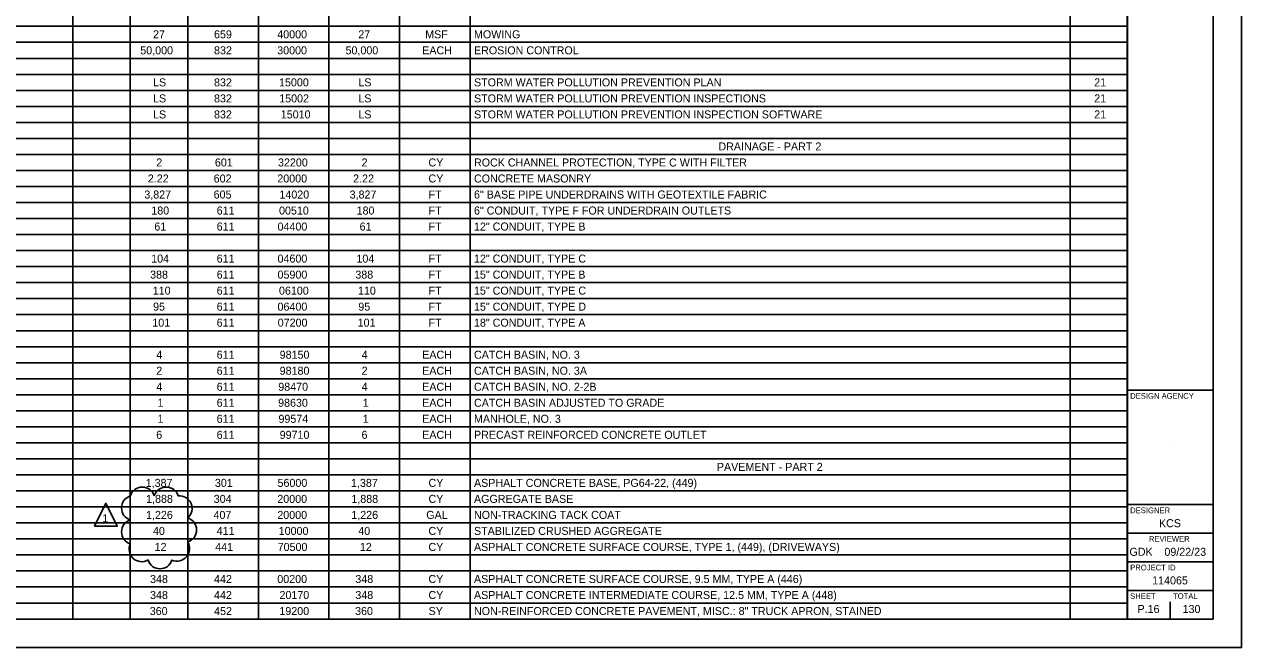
# Model space of a CAD drawing. Extents: x -156 to 77, y 0 to 24.
# Drawn here: x 12.71 to 34, y 0 to 10.89 of the extents above; entities that cross this region are included whole.
import ezdxf

# ---------------------------------------------------------------- set-up
doc = ezdxf.new("R2010")
doc.units = 0
for name, color, linetype in [('Default', 7, 'Continuous'), ('MU_Markup_Cloud', 7, 'Continuous'), ('SH_Border', 7, 'Continuous'), ('SH_Cut_Line', 7, 'Continuous'), ('SH_Data', 7, 'Continuous')]:
    doc.layers.add(name, color=color, linetype=linetype)

msp = doc.modelspace()

# ---------------------------------------------------------------- linework, layer by layer
at = {"layer": 'Default'}
for p, q in [((13.556, 21.5), (13.556, 0.5)), ((15.566, 21.5), (15.566, 0.5)), ((16.801, 21.5), (16.801, 0.5)), ((18.036, 21.5), (18.036, 0.5)), ((19.272, 21.5), (19.272, 0.5)), ((20.507, 21.5), (20.507, 0.5)), ((30.999, 21.5), (30.999, 0.5)), ((32.004, 21.5), (32.004, 0.5)), ((14.561, 20.94), (14.561, 0.5)), ((1.5, 10.86), (32.004, 10.86)), ((1.5, 10.58), (32.004, 10.58)), ((1.5, 10.3), (32.004, 10.3)), ((1.5, 10.02), (32.004, 10.02)), ((1.5, 9.74), (32.004, 9.74)), ((1.5, 9.46), (32.004, 9.46)), ((1.5, 9.18), (32.004, 9.18)), ((1.5, 8.9), (32.004, 8.9)), ((1.5, 8.62), (32.004, 8.62)), ((1.5, 8.34), (32.004, 8.34)), ((1.5, 8.06), (32.004, 8.06)), ((1.5, 7.78), (32.004, 7.78)), ((1.5, 7.5), (32.004, 7.5)), ((1.5, 7.22), (32.004, 7.22)), ((1.5, 6.94), (32.004, 6.94)), ((1.5, 6.66), (32.004, 6.66)), ((1.5, 6.38), (32.004, 6.38)), ((1.5, 6.1), (32.004, 6.1)), ((1.5, 5.82), (32.004, 5.82)), ((1.5, 5.54), (32.004, 5.54)), ((1.5, 5.26), (32.004, 5.26)), ((1.5, 4.98), (32.004, 4.98)), ((1.5, 4.7), (32.004, 4.7)), ((1.5, 4.42), (32.004, 4.42)), ((1.5, 4.14), (32.004, 4.14)), ((1.5, 3.86), (32.004, 3.86)), ((1.5, 3.58), (32.004, 3.58)), ((1.5, 3.3), (32.004, 3.3)), ((1.5, 3.02), (32.004, 3.02)), ((1.5, 2.74), (32.004, 2.74)), ((1.5, 2.46), (32.004, 2.46)), ((1.5, 2.18), (32.004, 2.18)), ((1.5, 1.9), (32.004, 1.9)), ((1.5, 1.62), (32.004, 1.62)), ((1.5, 1.34), (32.004, 1.34)), ((1.5, 1.06), (32.004, 1.06)), ((1.5, 0.78), (32.004, 0.78)), ((1.5, 0.5), (32.004, 0.5))]:
    msp.add_line(p, q, dxfattribs=at)
at = {"layer": 'MU_Markup_Cloud'}
msp.add_lwpolyline([(13.934, 2.123), (14.134, 2.523), (14.334, 2.123)], close=True, dxfattribs=at)
for centre, start, end in [((14.771, 2.586), 17.5, 162.5), ((15.19, 2.586), 17.5, 162.5), ((14.628, 2.442), 107.5, 252.5), ((15.422, 2.433), 310.8844, 95.8844), ((14.628, 2.023), 107.5, 252.5), ((15.5, 2.058), 287.5, 72.5), ((14.761, 1.722), 155.2877, 300.2877), ((15.379, 1.733), 246.4801, 31.4801), ((15.081, 1.598), 197.5, 342.5)]:
    msp.add_arc(centre, 0.22, start, end, dxfattribs=at)
at = {"layer": 'SH_Border'}
for p, q in [((32, 0.5), (32, 21.5)), ((32, 4.5), (33.5, 4.5)), ((32, 2.5), (33.5, 2.5)), ((32, 2), (33.5, 2)), ((32, 1.5), (33.5, 1.5)), ((32, 1), (33.5, 1))]:
    msp.add_line(p, q, dxfattribs=at)
msp.add_lwpolyline([(1.5, 21.5), (33.5, 21.5), (33.5, 0.5), (1.5, 0.5)], close=True, dxfattribs=at)
at = {"layer": 'SH_Cut_Line'}
msp.add_lwpolyline([(0, 0), (34, 0), (34, 22), (0, 22)], close=True, dxfattribs=at)
at = {"layer": 'SH_Data'}
for p, q in [((32.75, 3.5), (32.75, 3.5)), ((32.375, 0.675), (32.375, 0.675)), ((32.75, 0.5), (32.75, 0.8))]:
    msp.add_line(p, q, dxfattribs=at)

# ---------------------------------------------------------------- texts
at = {"layer": 'Default'}
for s, p in [('27', (14.959, 10.65)), ('659', (16.026, 10.65)), ('40000', (17.132, 10.65)), ('27', (18.549, 10.65)), ('MSF', (19.719, 10.65)), ('MOWING', (20.573, 10.65)), ('50,000', (14.736, 10.37)), ('832', (16.026, 10.37)), ('30000', (17.131, 10.37)), ('50,000', (18.326, 10.37)), ('EACH', (19.667, 10.37)), ('EROSION CONTROL', (20.573, 10.37)), ('LS', (14.959, 9.81)), ('832', (16.026, 9.81)), ('15000', (17.163, 9.81)), ('LS', (18.55, 9.81)), ('STORM WATER POLLUTION PREVENTION PLAN', (20.573, 9.81)), ('21', (31.421, 9.81)), ('LS', (14.959, 9.53)), ('832', (16.026, 9.53)), ('15002', (17.166, 9.53)), ('LS', (18.55, 9.53)), ('STORM WATER POLLUTION PREVENTION INSPECTIONS', (20.573, 9.53)), ('21', (31.421, 9.53)), ('LS', (14.959, 9.25)), ('832', (16.026, 9.25)), ('15010', (17.194, 9.25)), ('LS', (18.55, 9.25)), ('STORM WATER POLLUTION PREVENTION INSPECTION SOFTWARE', (20.573, 9.25)), ('21', (31.421, 9.25)), ('DRAINAGE - PART 2', (24.848, 8.69)), ('2', (15.016, 8.41)), ('601', (16.041, 8.41)), ('32200', (17.145, 8.41)), ('2', (18.607, 8.41)), ('CY', (19.777, 8.41)), ('ROCK CHANNEL PROTECTION, TYPE C WITH FILTER', (20.573, 8.41)), ('2.22', (14.868, 8.13)), ('602', (16.02, 8.13)), ('20000', (17.133, 8.13)), ('2.22', (18.459, 8.13)), ('CY', (19.777, 8.13)), ('CONCRETE MASONRY', (20.573, 8.13)), ('3,827', (14.807, 7.85)), ('605', (16.019, 7.85)), ('14020', (17.17, 7.85)), ('3,827', (18.398, 7.85)), ('FT', (19.779, 7.85)), ('6" BASE PIPE UNDERDRAINS WITH GEOTEXTILE FABRIC', (20.573, 7.85)), ('180', (14.929, 7.57)), ('611', (16.072, 7.57)), ('00510', (17.163, 7.57)), ('180', (18.52, 7.57)), ('FT', (19.779, 7.57)), ('6" CONDUIT, TYPE F FOR UNDERDRAIN OUTLETS', (20.573, 7.57)), ('61', (14.982, 7.29)), ('611', (16.072, 7.29)), ('04400', (17.137, 7.29)), ('61', (18.572, 7.29)), ('FT', (19.779, 7.29)), ('12" CONDUIT, TYPE B', (20.573, 7.29)), ('104', (14.927, 6.73)), ('611', (16.072, 6.73)), ('04600', (17.137, 6.73)), ('104', (18.517, 6.73)), ('FT', (19.779, 6.73)), ('12" CONDUIT, TYPE C', (20.573, 6.73)), ('388', (14.908, 6.45)), ('611', (16.072, 6.45)), ('05900', (17.137, 6.45)), ('388', (18.498, 6.45)), ('FT', (19.779, 6.45)), ('15" CONDUIT, TYPE B', (20.573, 6.45)), ('110', (14.954, 6.17)), ('611', (16.072, 6.17)), ('06100', (17.162, 6.17)), ('110', (18.544, 6.17)), ('FT', (19.779, 6.17)), ('15" CONDUIT, TYPE C', (20.573, 6.17)), ('95', (14.96, 5.89)), ('611', (16.072, 5.89)), ('06400', (17.137, 5.89)), ('95', (18.55, 5.89)), ('FT', (19.779, 5.89)), ('15" CONDUIT, TYPE D', (20.573, 5.89)), ('101', (14.947, 5.61)), ('611', (16.072, 5.61)), ('07200', (17.14, 5.61)), ('101', (18.538, 5.61)), ('FT', (19.779, 5.61)), ('18" CONDUIT, TYPE A', (20.573, 5.61)), ('4', (15.017, 5.05)), ('611', (16.072, 5.05)), ('98150', (17.174, 5.05)), ('4', (18.608, 5.05)), ('EACH', (19.667, 5.05)), ('CATCH BASIN, NO. 3', (20.573, 5.05)), ('2', (15.016, 4.77)), ('611', (16.072, 4.77)), ('98180', (17.174, 4.77)), ('2', (18.607, 4.77)), ('EACH', (19.667, 4.77)), ('CATCH BASIN, NO. 3A', (20.573, 4.77)), ('4', (15.017, 4.49)), ('611', (16.072, 4.49)), ('98470', (17.15, 4.49)), ('4', (18.608, 4.49)), ('EACH', (19.667, 4.49)), ('CATCH BASIN, NO. 2-2B', (20.573, 4.49)), ('1', (15.037, 4.21)), ('611', (16.072, 4.21)), ('98630', (17.147, 4.21)), ('1', (18.628, 4.21)), ('EACH', (19.667, 4.21)), ('CATCH BASIN ADJUSTED TO GRADE', (20.573, 4.21)), ('1', (15.037, 3.93)), ('611', (16.072, 3.93)), ('99574', (17.153, 3.93)), ('1', (18.628, 3.93)), ('EACH', (19.667, 3.93)), ('MANHOLE, NO. 3', (20.573, 3.93)), ('6', (15.015, 3.65)), ('611', (16.072, 3.65)), ('99710', (17.174, 3.65)), ('6', (18.606, 3.65)), ('EACH', (19.667, 3.65)), ('PRECAST REINFORCED CONCRETE OUTLET', (20.573, 3.65)), ('PAVEMENT - PART 2', (24.821, 3.09)), ('1,387', (14.831, 2.81)), ('301', (16.041, 2.81)), ('56000', (17.137, 2.81)), ('1,387', (18.422, 2.81)), ('CY', (19.777, 2.81)), ('ASPHALT CONCRETE BASE, PG64-22, (449)', (20.573, 2.81)), ('1,888', (14.838, 2.53)), ('304', (16.021, 2.53)), ('20000', (17.133, 2.53)), ('1,888', (18.428, 2.53)), ('CY', (19.777, 2.53)), ('AGGREGATE BASE', (20.573, 2.53)), ('1,226', (14.837, 2.25)), ('407', (16.017, 2.25)), ('20000', (17.133, 2.25)), ('1,226', (18.427, 2.25)), ('GAL', (19.738, 2.25)), ('NON-TRACKING TACK COAT', (20.573, 2.25)), ('40', (14.958, 1.97)), ('411', (16.072, 1.97)), ('10000', (17.157, 1.97)), ('40', (18.549, 1.97)), ('CY', (19.777, 1.97)), ('STABILIZED CRUSHED AGGREGATE', (20.573, 1.97)), ('12', (14.987, 1.69)), ('441', (16.047, 1.69)), ('70500', (17.139, 1.69)), ('12', (18.577, 1.69)), ('CY', (19.777, 1.69)), ('ASPHALT CONCRETE SURFACE COURSE, TYPE 1, (449), (DRIVEWAYS)', (20.573, 1.69)), ('348', (14.907, 1.13)), ('442', (16.026, 1.13)), ('00200', (17.133, 1.13)), ('348', (18.498, 1.13)), ('CY', (19.777, 1.13)), ('ASPHALT CONCRETE SURFACE COURSE, 9.5 MM, TYPE A (446)', (20.573, 1.13)), ('348', (14.907, 0.85)), ('442', (16.026, 0.85)), ('20170', (17.171, 0.85)), ('348', (18.498, 0.85)), ('CY', (19.777, 0.85)), ('ASPHALT CONCRETE INTERMEDIATE COURSE, 12.5 MM, TYPE A (448)', (20.573, 0.85)), ('360', (14.902, 0.57)), ('452', (16.027, 0.57)), ('19200', (17.169, 0.57)), ('360', (18.493, 0.57)), ('SY', (19.779, 0.57)), ('NON-REINFORCED CONCRETE PAVEMENT, MISC.: 8" TRUCK APRON, STAINED', (20.573, 0.57))]:
    msp.add_text(s, height=0.14, dxfattribs=at).set_placement(p)
at = {"layer": 'MU_Markup_Cloud'}
msp.add_text('1', height=0.14, dxfattribs=at).set_placement((14.072, 2.19))
at = {"layer": 'SH_Data'}
for s, height, p in [('DESIGN AGENCY', 0.1, (32.05, 4.35)), ('DESIGNER', 0.1, (32.05, 2.35)), ('KCS', 0.14, (32.554, 2.105)), ('REVIEWER', 0.1, (32.378, 1.85)), ('GDK', 0.14, (32.038, 1.605)), ('09/22/23', 0.14, (32.649, 1.605)), ('PROJECT ID', 0.1, (32.05, 1.35)), ('114065', 0.14, (32.435, 1.105)), ('SHEET', 0.1, (32.05, 0.85)), ('TOTAL', 0.1, (32.8, 0.85)), ('P.16', 0.14, (32.178, 0.605)), ('130', 0.14, (32.967, 0.605))]:
    msp.add_text(s, height=height, dxfattribs=at).set_placement(p)

doc.saveas('drawing.dxf')
